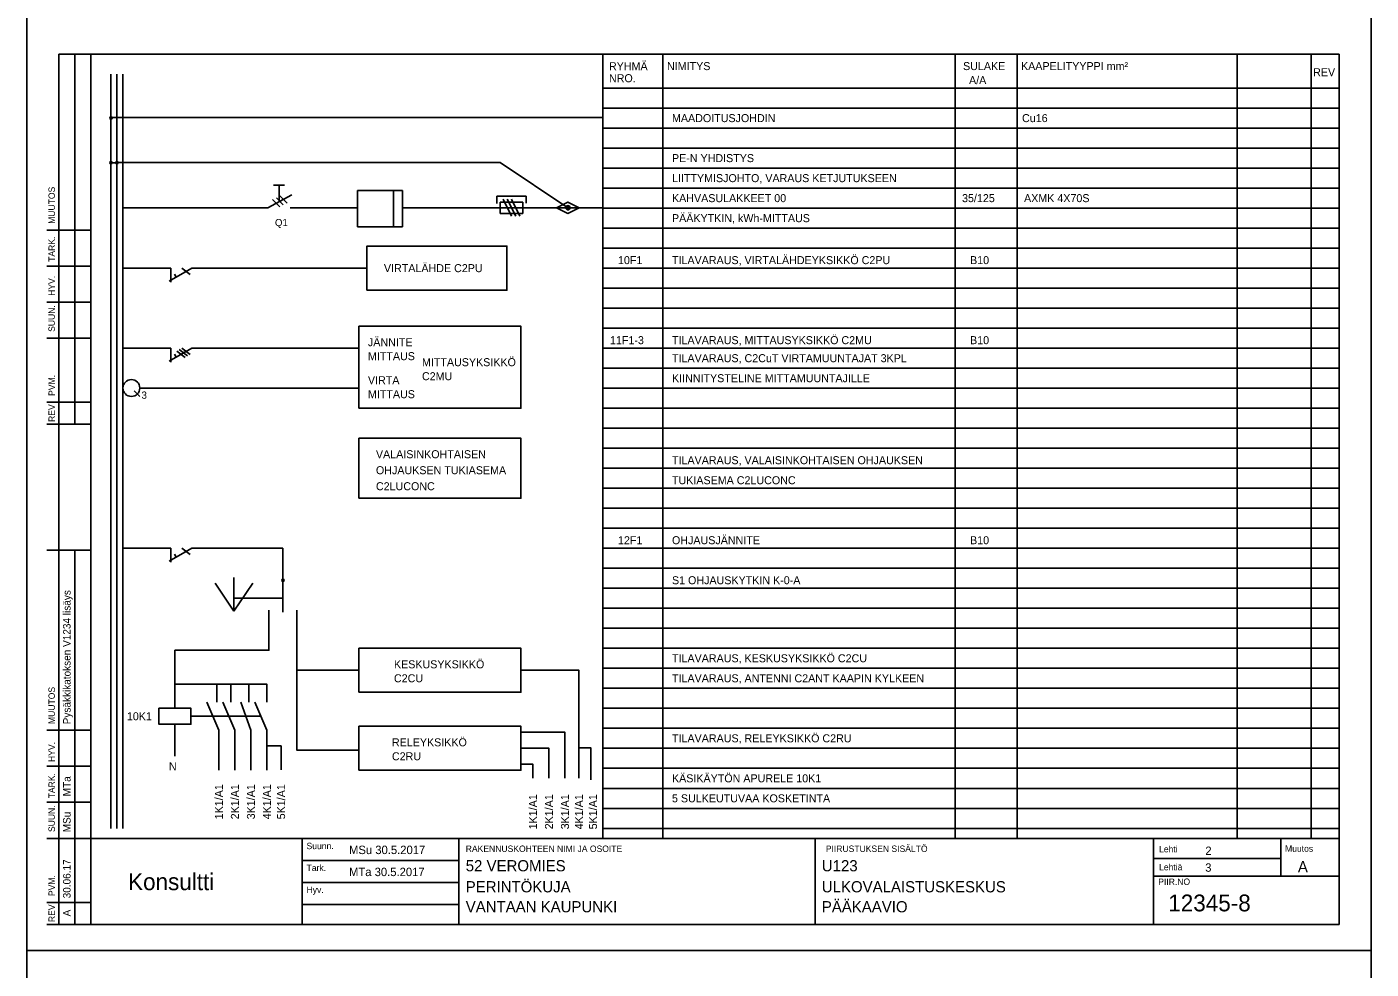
# Model space of a CAD drawing. Extents: x 0 to 420, y -594 to 297.
# Drawn here: x 0 to 420, y -302.9 to -8.5 of the extents above; entities that cross this region are included whole.
import ezdxf

# ---------------------------------------------------------------- set-up
doc = ezdxf.new("R2010")
doc.units = 0
for name, color, linetype in [('SAH3340_E0', 7, 'Continuous'), ('SK100J', 7, 'Continuous'), ('SK100K', 7, 'Continuous'), ('SPNODE', 7, 'Continuous'), ('TEKSTI', 7, 'Continuous')]:
    doc.layers.add(name, color=color, linetype=linetype)

# ---------------------------------------------------------------- blocks, each defined once
blk = doc.blocks.new('taulukko')
for p, q in [((180, 35), (180, 280)), ((198.75, 35), (198.75, 279.96)), ((290, 35), (290, 280)), ((309.38, 35), (309.38, 280)), ((378.12, 35), (378.12, 280)), ((401.25, 35), (401.25, 279.96)), ((30, 38.12), (30, 273.75)), ((180, 269.37), (410, 269.37)), ((180, 256.87), (410, 256.87)), ((180, 244.37), (410, 244.37)), ((180, 231.87), (410, 231.87)), ((180, 219.37), (410, 219.37)), ((180, 206.87), (410, 206.87)), ((180, 194.37), (410, 194.37)), ((180, 181.87), (410, 181.87)), ((180, 169.37), (410, 169.37)), ((180, 156.87), (410, 156.87)), ((180, 144.37), (410, 144.37)), ((180, 131.87), (410, 131.87)), ((180, 119.37), (410, 119.37)), ((180, 106.87), (410, 106.87)), ((180, 94.37), (410, 94.37)), ((180, 81.87), (410, 81.87)), ((180, 69.37), (410, 69.37)), ((180, 56.87), (410, 56.87)), ((180, 44.37), (410, 44.37))]:
    blk.add_line(p, q)
for points in [[(26.25, 273.75), (26.25, 38.12)], [(28.12, 273.75), (28.12, 38.12)], [(180, 263.12), (410, 263.12)], [(180, 250.62), (410, 250.62)], [(180, 238.12), (410, 238.12)], [(180, 225.62), (410, 225.62)], [(180, 213.12), (410, 213.12)], [(180, 200.62), (410, 200.62)], [(180, 188.12), (410, 188.12)], [(180, 175.62), (410, 175.62)], [(180, 163.12), (410, 163.12)], [(180, 150.62), (410, 150.62)], [(180, 138.12), (410, 138.12)], [(180, 125.62), (410, 125.62)], [(180, 113.12), (410, 113.12)], [(180, 100.62), (410, 100.62)], [(180, 88.12), (410, 88.12)], [(180, 75.62), (410, 75.62)], [(180, 63.12), (410, 63.12)], [(180, 50.62), (410, 50.62)], [(180, 38.12), (410, 38.12)]]:
    blk.add_lwpolyline(points)
for s, p in [('RYHMÄ', (181.87, 274.97)), ('NIMITYS', (200, 275)), ('SULAKE', (292.5, 275)), ('KAAPELITYYPPI mm²', (310.62, 275)), ('NRO.', (181.87, 271.22)), ('A/A', (294.38, 270.62)), ('REV', (401.88, 273.09))]:
    blk.add_text(s, height=2.5).set_placement(p)
blk = doc.blocks.new('KLI101P')
at = {"layer": 'SK100J'}
blk.add_lwpolyline([(2.5, 0), (0, -1.25), (-2.5, 0), (0, 1.25), (2.5, 0)], dxfattribs=at)
blk.add_circle((0, 0), 0.469, dxfattribs=at)
for start, end in [(0, 180), (180, 0)]:
    blk.add_arc((0, 0), 0.281, start, end, dxfattribs=at)
blk = doc.blocks.new('A$C1A823D8E')
for p, q in [((7.36, 8), (15.36, 8)), ((7.36, 0), (7.36, 8)), ((15.36, 8), (17.36, 8)), ((15.36, 8), (15.36, 0)), ((17.36, 8), (17.36, 0)), ((15.36, 0), (7.36, 0)), ((17.36, 0), (15.36, 0))]:
    blk.add_line(p, q)
blk = doc.blocks.new('3V')
at = {"layer": 'SK100J'}
for p, q in [((-0.66, -1.53), (-2.17, 0.02)), ((0.18, -1.14), (-1.41, 0.48)), ((-1.42, -1.99), (-3.01, -0.37))]:
    blk.add_line(p, q, dxfattribs=at)
blk = doc.blocks.new('A$C23961C6B')
for p, q in [((5, 3.75), (10.36, 6.61)), ((5, 3.75), (0, 3.75)), ((15, 3.75), (10, 3.75))]:
    blk.add_line(p, q)
at = {"layer": 'SK100J'}
blk.add_line((8.75, 8.75), (6.25, 8.75), dxfattribs=at)
at = {"layer": 'SK100K'}
blk.add_line((7.5, 8.75), (7.5, 5.08), dxfattribs=at)
at = {"layer": 'SK100J', "rotation": 180}
blk.add_blockref('3V', (6.27, 4.42), dxfattribs=at)
blk = doc.blocks.new('A$C27D17FDD')
for p, q in [((10, 3.12), (5, 3.12)), ((5, 0.62), (5, 3.12)), ((5, 3.12), (5, 0.62)), ((10, 0.62), (10, 3.12)), ((15, 1.87), (0, 1.87)), ((5, 0.62), (10, 0.62))]:
    blk.add_line(p, q)
at = {"layer": 'SK100J'}
for p, q in [((7.5, 0), (5.63, 3.75)), ((8.44, 0), (6.56, 3.75)), ((9.38, 0), (7.5, 3.75))]:
    blk.add_line(p, q, dxfattribs=at)
blk = doc.blocks.new('F14')
for points in [[(15, 0), (0, 0)], [(21.5, 0), (14.48, -4.03)], [(15, 0), (15, -4.38)], [(21.5, 0), (50, 0)], [(16.64, -2.78), (16.08, -1.82)], [(19.44, -2.9), (16.83, -0.94)], [(20.14, -2.38), (17.53, -0.42)], [(21.06, -1.96), (18.45, 0)]]:
    blk.add_lwpolyline(points)
blk = doc.blocks.new('FF13')
for points in [[(15, 0), (0, 0)], [(21.5, 0), (14.48, -4.03)], [(15, 0), (15, -4.38)], [(21.5, 0), (50, 0)], [(16.64, -2.78), (16.08, -1.82)], [(21.06, -1.96), (18.45, 0)]]:
    blk.add_lwpolyline(points)
blk = doc.blocks.new('POINT_DISPLAY')
blk.add_line((0, 0), (0, 0))
blk = doc.blocks.new('PKA102P')
for q in [(0, 3.75), (-4.16, 2.49), (4.16, 2.49)]:
    blk.add_line((0, -3.75), q)
at = {"layer": 'SPNODE'}
blk.add_blockref('POINT_DISPLAY', (0, 0), dxfattribs=at)

msp = doc.modelspace()

# ---------------------------------------------------------------- linework, layer by layer
for p, q in [((0, 0), (0, -297)), ((420, -297), (420, 0)), ((10, -17), (10, -288.88)), ((15, -132.62), (15, -17)), ((20, -17), (20, -288.88)), ((410, -17), (20, -17)), ((410, -288.88), (410, -17)), ((26.25, -36.81), (179.61, -36.81)), ((103.29, -65.01), (86.25, -65.01)), ((140.84, -65.01), (117.39, -65.01)), ((179.61, -65.01), (140.84, -65.01)), ((15, -288.88), (15, -172)), ((410, -264.5), (410, -212)), ((20, -262), (410, -262)), ((86, -262), (86, -288.88)), ((135, -262), (135, -288.88)), ((246.25, -288.88), (246.25, -262)), ((352, -288.88), (352, -262)), ((391.75, -273.78), (391.75, -262)), ((351.88, -268.25), (391.75, -268.25)), ((86, -268.88), (135, -268.88)), ((86, -275.75), (135, -275.75)), ((351.88, -273.8), (410, -273.8)), ((86, -282.62), (135, -282.62)), ((20, -288.88), (410, -288.88)), ((0, -297), (0, -594)), ((420, -297), (0, -297)), ((420, -594), (420, -297))]:
    msp.add_line(p, q)
for points in [[(10, -17), (20.14, -17)], [(26.25, -50.92), (28.12, -50.92)], [(169.04, -65.01), (147.89, -50.91), (28.12, -50.91)], [(146.84, -63.65), (146.84, -61.42), (155.97, -61.42), (155.97, -63.59)], [(68.75, -65.01), (30, -65.01)], [(6.25, -72), (20, -72)], [(6.25, -83.25), (20, -83.25)], [(79.38, -83.88), (106.25, -83.88)], [(6.25, -94.5), (20, -94.5)], [(6.25, -105.75), (20, -105.75)], [(79.38, -108.88), (103.75, -108.88)], [(103.75, -121.38), (35.3, -121.38)], [(6.25, -125.75), (20, -125.75)], [(6.25, -132.62), (20.14, -132.62)], [(6.25, -172), (20, -172)], [(80, -171.38), (80, -181.38)], [(80, -181.38), (80, -191.38)], [(80, -187), (64.7, -187)], [(75.62, -190.75), (75.62, -203.25), (46.25, -203.25), (46.25, -221.38)], [(84.38, -209.5), (84.38, -190.75)], [(84.38, -209.5), (84.38, -234.5), (103.75, -234.5)], [(103.75, -209.5), (84.38, -209.5)], [(154.38, -209.5), (172.5, -209.5), (172.5, -243.25)], [(46.25, -213.88), (75, -213.88), (75, -219.5)], [(59.38, -219.5), (59.38, -213.88)], [(63.75, -219.5), (63.75, -213.88)], [(69.38, -219.5), (69.38, -213.88)], [(41.25, -221.38), (51.25, -221.38), (51.25, -226.38), (41.25, -226.38), (41.25, -221.38), (41.25, -221.38)], [(60, -228.25), (56.25, -219.5)], [(65, -228.25), (61.25, -219.5)], [(70, -228.25), (66.88, -219.5)], [(75, -228.25), (71.25, -219.5)], [(46.25, -226.38), (46.25, -236.38)], [(73.12, -223.88), (51.25, -223.88)], [(6.25, -228.25), (20, -228.25)], [(60, -228.25), (60, -240.75)], [(65, -228.25), (65, -240.75)], [(70, -228.25), (70, -240.75)], [(75, -228.25), (75, -240.75)], [(154.38, -228.88), (168.12, -228.88), (168.12, -243.25)], [(75, -233.12), (79.42, -233.12), (79.42, -240.62)], [(163.12, -243.25), (163.12, -233.88), (154.38, -233.88)], [(172.5, -233.75), (176.25, -233.75), (176.25, -243.75)], [(154.38, -238.88), (158.12, -238.88), (158.12, -243.25)], [(6.25, -239.5), (20, -239.5)], [(6.25, -250.75), (20, -250.75)], [(6.25, -262), (20, -262)], [(6.25, -282), (20, -282)], [(20, -288.88), (6.25, -288.88)], [(0, -297), (420, -297)]]:
    msp.add_lwpolyline(points)
for points in [[(106.25, -90.75), (106.25, -77), (150, -77), (150, -90.75)], [(103.75, -127.62), (103.75, -102), (154.38, -102), (154.38, -127.62)], [(103.75, -155.75), (103.75, -137), (154.38, -137), (154.38, -155.75)], [(103.75, -216.38), (103.75, -202.62), (154.38, -202.62), (154.38, -216.38)], [(103.75, -240.75), (103.75, -227), (154.38, -227), (154.38, -240.75)]]:
    msp.add_lwpolyline(points, close=True)
for centre, start, end in [((26.25, -37), 0, 180), ((26.25, -37), 180, 0), ((26.25, -50.92), 0, 180), ((26.25, -50.92), 180, 0), ((28.12, -50.92), 0, 180), ((28.12, -50.92), 180, 0), ((80, -181.38), 0, 180), ((80, -181.38), 180, 0)]:
    msp.add_arc(centre, 0.377, start, end)
at = {"layer": 'SAH3340_E0'}
msp.add_line((33.54, -122.2), (35.3, -123.97), dxfattribs=at)
msp.add_circle((32.65, -121.32), 2.64, dxfattribs=at)

# ---------------------------------------------------------------- block references
for name, p in [('taulukko', (0, -297)), ('FF13', (30, -83.88)), ('F14', (30, -108.88)), ('FF13', (30, -171.38))]:
    msp.add_blockref(name, p)
at = {"xscale": 1.41, "yscale": 1.41}
for name, p in [('A$C23961C6B', (68.2, -70.29)), ('A$C1A823D8E', (92.9, -70.92)), ('KLI101P', (169.04, -65.01))]:
    msp.add_blockref(name, p, dxfattribs=at)
at = {"layer": 'SAH3340_E0', "xscale": 1.41, "yscale": 1.41}
for name, p in [('A$C27D17FDD', (140.84, -67.65)), ('PKA102P', (64.7, -185.75))]:
    msp.add_blockref(name, p, dxfattribs=at)

# ---------------------------------------------------------------- texts
for s, height, p in [('MAADOITUSJOHDIN', 2.5, (201.56, -38.25)), ('Cu16', 2.5, (310.94, -38.25)), ('PE-N YHDISTYS', 2.5, (201.56, -50.75)), ('LIITTYMISJOHTO, VARAUS KETJUTUKSEEN', 2.5, (201.56, -57)), ('KAHVASULAKKEET 00', 2.5, (201.56, -63.25)), ('35/125', 2.5, (292.19, -63.25)), ('AXMK 4X70S', 2.5, (311.56, -63.25)), ('PÄÄKYTKIN, kWh-MITTAUS', 2.5, (201.56, -69.5)), ('Q1', 2.256, (77.5, -70.75)), ('TILAVARAUS, VIRTALÄHDEYKSIKKÖ C2PU', 2.5, (201.56, -82.62)), ('VIRTALÄHDE C2PU', 2.5, (111.56, -85.12)), ('10F1', 2.5, (184.69, -82.62)), ('B10', 2.5, (294.69, -82.62)), ('TILAVARAUS, MITTAUSYKSIKKÖ C2MU', 2.5, (201.56, -107.62)), ('JÄNNITE', 2.5, (106.56, -108.25)), ('11F1-3', 2.5, (182.19, -107.62)), ('B10', 2.5, (294.69, -107.62)), ('MITTAUS', 2.5, (106.56, -112.62)), ('MITTAUSYKSIKKÖ', 2.5, (123.44, -114.5)), ('TILAVARAUS, C2CuT VIRTAMUUNTAJAT 3KPL', 2.5, (201.56, -113.25)), ('C2MU', 2.5, (123.44, -118.88)), ('KIINNITYSTELINE MITTAMUUNTAJILLE', 2.5, (201.56, -119.5)), ('VIRTA', 2.5, (106.56, -120.12)), ('MITTAUS', 2.5, (106.56, -124.5)), ('VALAISINKOHTAISEN', 2.5, (109.06, -143.25)), ('TILAVARAUS, VALAISINKOHTAISEN OHJAUKSEN', 2.5, (201.56, -145.12)), ('OHJAUKSEN TUKIASEMA', 2.5, (109.06, -148.25)), ('C2LUCONC', 2.5, (109.06, -153.25)), ('TUKIASEMA C2LUCONC', 2.5, (201.56, -151.38)), ('12F1', 2.5, (184.69, -170.12)), ('OHJAUSJÄNNITE', 2.5, (201.56, -170.12)), ('B10', 2.5, (294.69, -170.12)), ('S1 OHJAUSKYTKIN K-0-A', 2.5, (201.56, -182.62)), ('TILAVARAUS, KESKUSYKSIKKÖ C2CU', 2.5, (201.56, -207)), ('KESKUSYKSIKKÖ', 2.5, (114.69, -208.88)), ('C2CU', 2.5, (114.69, -213.25)), ('TILAVARAUS, ANTENNI C2ANT KAAPIN KYLKEEN', 2.5, (201.56, -213.25)), ('10K1', 2.5, (31.25, -225.12)), ('RELEYKSIKKÖ', 2.5, (114.06, -233.25)), ('TILAVARAUS, RELEYKSIKKÖ C2RU', 2.5, (201.56, -232)), ('C2RU', 2.5, (114.06, -237.62)), ('N', 2.5, (44.38, -240.75)), ('KÄSIKÄYTÖN APURELE 10K1', 2.5, (201.56, -244.5)), ('5 SULKEUTUVAA KOSKETINTA', 2.5, (201.56, -250.75)), ('Suunn.', 2, (87.38, -265.38)), ('MSu 30.5.2017', 2.625, (100.66, -266.92)), ('RAKENNUSKOHTEEN NIMI JA OSOITE', 2, (137.12, -266.25)), ('PIIRUSTUKSEN SISÄLTÖ', 2, (249.62, -266.25)), ('Lehti', 2, (353.75, -266.38)), ('2', 2.62, (368.21, -267.2)), ('Muutos', 2, (393.12, -266.21)), ('52 VEROMIES', 3.5, (137.12, -272.31)), ('U123', 3.5, (248.38, -272.31)), ('Konsultti', 5.25, (31.62, -278.19)), ('Tark.', 2, (87.38, -272.2)), ('MTa 30.5.2017', 2.625, (100.66, -273.8)), ('Lehtiä', 2, (353.75, -272)), ('3', 2.62, (368.16, -272.44)), ('A', 3.5, (397.12, -272.62)), ('Hyv.', 2, (87.38, -279.07)), ('PERINTÖKUJA', 3.5, (137.12, -278.88)), ('ULKOVALAISTUSKESKUS', 3.5, (248.38, -278.88)), ('PIIR.NO', 2, (353.5, -276.55)), ('PÄÄKAAVIO', 3.5, (248.38, -285.12)), ('12345-8', 5.25, (356.62, -284.81)), ('VANTAAN KAUPUNKI', 3.5, (137.12, -285.12))]:
    msp.add_text(s, height=height).set_placement(p)
for s, height, p in [('MUUTOS', 2, (8.75, -70.03)), ('TARK.', 2, (8.75, -81.9)), ('HYV.', 2, (8.75, -92.53)), ('SUUN.', 2, (8.75, -103.78)), ('PVM.', 2, (8.75, -123.78)), ('REV', 2, (8.75, -131.9)), ('MUUTOS', 2, (8.75, -226.28)), ('HYV.', 2, (8.75, -238.15)), ('TARK.', 2, (8.75, -249.5)), ('1K1/A1', 2.5, (61.25, -256.06)), ('2K1/A1', 2.5, (66.25, -256.06)), ('3K1/A1', 2.5, (71.25, -256.06)), ('4K1/A1', 2.5, (76.25, -256.06)), ('5K1/A1', 2.5, (80.67, -256.06)), ('SUUN.', 2, (8.75, -260.03)), ('1K1/A1', 2.5, (159.38, -259.19)), ('2K1/A1', 2.5, (164.38, -259.19)), ('3K1/A1', 2.5, (169.38, -259.19)), ('4K1/A1', 2.5, (173.75, -259.19)), ('5K1/A1', 2.5, (178.12, -259.19)), ('PVM.', 2, (8.75, -280.03)), ('REV', 2, (8.75, -288.15))]:
    msp.add_text(s, height=height, rotation=90).set_placement(p)
at = {"layer": 'SAH3340_E0'}
msp.add_text('3', height=2.26, dxfattribs=at).set_placement((35.82, -124.67))
at = {"layer": 'TEKSTI'}
for s, p in [('Pysäkkikatoksen V1234 lisäys', (13.65, -226.38)), ('MTa', (13.65, -248.88)), ('MSu', (13.65, -260.12)), ('30.06.17', (13.65, -280.75)), ('A', (13.65, -286.38))]:
    msp.add_text(s, height=2.34, rotation=90, dxfattribs=at).set_placement(p)

doc.saveas('drawing.dxf')
